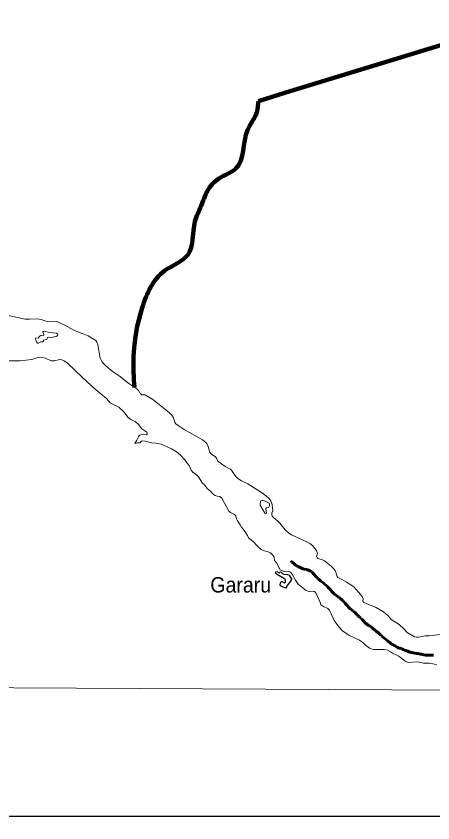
# Model space of a CAD drawing. Extents: x -1643653 to 4543381, y 1624270 to 13878484.
# Drawn here: x 701363 to 714916, y 8889633 to 8915829 of the extents above; entities that cross this region are included whole.
import ezdxf

# ---------------------------------------------------------------- set-up
doc = ezdxf.new("R2010")
doc.units = 0
doc.header["$LTSCALE"] = 200
doc.linetypes.add('LONG_DASH_SHORT_DASH', pattern=[9.9, 6, -1.2, 1.5, -1.2])
for name, color, linetype, lineweight in [('1', 7, 'Continuous', 13), ('21', 7, 'Continuous', 25), ('25', 7, 'Continuous', 13), ('3', 7, 'Continuous', 13), ('60', 7, 'Continuous', 13), ('7', 7, 'LONG_DASH_SHORT_DASH', 60), ('9', 7, 'Continuous', 90)]:
    doc.layers.add(name, color=color, linetype=linetype, lineweight=lineweight)
doc.layers.add('41', color=7, linetype='Continuous')

msp = doc.modelspace()

# ---------------------------------------------------------------- linework, layer by layer
at = {"layer": '1'}
msp.add_lwpolyline([(564751.7, 8894587.5), (664411.9, 8894209.9), (791388.5, 8893536.2)], dxfattribs=at)
at = {"layer": '21'}
msp.add_lwpolyline([(710323, 8897547.4), (710310.6, 8897510.9), (710262.7, 8897448.5), (710205.4, 8897388.1), (710179.6, 8897340.9), (710149.4, 8897265.1), (710140.8, 8897256.9), (710043.9, 8897288.4), (709961.7, 8897329.1), (709947.6, 8897363.1), (709961.6, 8897429.2), (709984.2, 8897470), (709989.6, 8897472.6), (710012.7, 8897467.5), (710090.3, 8897425.2), (710122.4, 8897447.6), (710126, 8897519.8), (710103.3, 8897545.3), (710035.6, 8897588.8), (709826.1, 8897706.4), (709795.6, 8897744), (709810.8, 8897781.5), (709838, 8897800.1), (709914.9, 8897754.6), (709934.2, 8897760.9), (709942.3, 8897776.2), (709957.1, 8897785.6), (709980.8, 8897774.5), (710029.3, 8897733.8), (710072, 8897710.7), (710184.3, 8897701.5), (710239.2, 8897671.8), (710278.2, 8897623.4), (710322, 8897552.2)], close=True, dxfattribs=at)
at = {"layer": '25'}
for points in [[(699730.1, 8905870.1), (699833.6, 8905937.4), (700049.1, 8906011), (700564.9, 8906093.9), (701005.2, 8906113.6), (701154.5, 8906101.4), (701659.8, 8905992.8), (701803.5, 8905986.5), (702058.9, 8906003.4), (702175.9, 8905983.8), (702373, 8905910.6), (702436.8, 8905905.5), (702682, 8905912.8), (702942.6, 8905799.8), (703043.5, 8905742.3)], [(703043.5, 8905742.3), (703240.1, 8905630.3), (703386.8, 8905567), (703544.9, 8905514.5)], [(703544.9, 8905514.5), (703544.9, 8905514.5), (703708.6, 8905443.2), (703903.3, 8905333.4), (703950.4, 8905293.2), (703983.7, 8905242.4), (704017.5, 8905157.8), (704100.5, 8904727.4), (704116.7, 8904678.1), (704169.6, 8904585.4), (704276.9, 8904471.4), (704483.1, 8904302.2), (704709.8, 8904149.5), (705025.3, 8903904.5), (705294.1, 8903731.4), (705355.9, 8903661.9), (705397.8, 8903579.9), (705416.3, 8903559.4), (705456.6, 8903537.1), (705545.2, 8903528.8), (705574.6, 8903518.8), (705812.1, 8903380.7), (705964.1, 8903265.1), (706335.8, 8902958.3), (706429, 8902870.5), (706478.4, 8902782.6), (706522.3, 8902644.6), (706561.4, 8902592.6), (706627.5, 8902537.3), (706829.4, 8902410.4), (707426.7, 8902069.6), (707536.7, 8901989.7), (707580.8, 8901930.1), (707613.5, 8901857.8), (707638, 8901734), (707661.4, 8901666.3), (707707.1, 8901616.1), (707849, 8901513.6), (707889.3, 8901456.4), (707921.2, 8901374.1), (708164.6, 8901203.2), (708234, 8901164.4), (708282.6, 8901144)], [(702004.3, 8904719), (701870.4, 8904678.1), (701577.9, 8904651), (701498, 8904635.9)], [(703520.5, 8904092.8), (703035.9, 8904557.4), (702930.4, 8904637.9), (702854, 8904670.9), (702784.7, 8904678.3), (702603.6, 8904639.4), (702499.6, 8904635.8), (702318.3, 8904724.9), (702212.1, 8904749.4), (702106.6, 8904750.3), (702004.3, 8904719)], [(701498, 8904635.9), (701073.3, 8904639.9), (700893.6, 8904612.2), (700683.7, 8904613.8), (700499, 8904578.5), (700435.5, 8904574.2), (700368.5, 8904593.8)], [(704418.9, 8903273.5), (704303.8, 8903412.4), (703938.7, 8903713.3), (703520.5, 8904092.8)], [(705417, 8902230.5), (705468.7, 8902243.1), (705601.7, 8902236.3), (705626.1, 8902249.9), (705630.1, 8902294), (705613.1, 8902318.7), (705450.5, 8902433.4), (705338.6, 8902571.8), (705237.8, 8902662.7), (705098.5, 8902732.8), (705008.4, 8902794.2), (704859.8, 8902995.3), (704700.7, 8903136.3), (704418.9, 8903273.5)], [(705223.5, 8901956.6), (705285.9, 8902055.5), (705327.2, 8902145.4), (705340, 8902163.9), (705340, 8902163.9)], [(705340, 8902163.9), (705380.2, 8902221.5), (705417, 8902230.5)], [(706917, 8901328.8), (706845.7, 8901419), (706706.3, 8901570.6), (706577.5, 8901683.7), (706418, 8901776), (706077.6, 8901924.8), (705902.1, 8901964.8), (705769.4, 8901975.3), (705559.8, 8902024.1), (705462.6, 8902034.1), (705436.9, 8902022.7), (705383.9, 8901976.1), (705305.7, 8901975.9), (705223.5, 8901956.6)], [(708884.8, 8898960.2), (708812.9, 8899081.1), (708692, 8899230.3), (708649.9, 8899313.3), (708562.2, 8899440.2), (708534.2, 8899502.9), (708503.8, 8899608.4), (708465.9, 8899644.1), (708336.8, 8899710.3), (708284.4, 8899750.1), (708047.8, 8900175.7), (707990.8, 8900226.5), (707897.1, 8900236.8), (707831, 8900260), (707784.3, 8900295.7), (707679.2, 8900403.7), (707579.3, 8900485.4), (707498.4, 8900600.3), (707426.9, 8900668.2), (707296.2, 8900870.2), (707244.9, 8900923.6), (707114.9, 8901025.9), (707060.8, 8901088.8), (706991.1, 8901234.8), (706917, 8901328.8)], [(708282.6, 8901144), (708331.2, 8901123.5), (708369.6, 8901088.6), (708444.9, 8900971.6), (708520.8, 8900871.2), (708577.2, 8900819.4), (708690.2, 8900735.5), (708901.9, 8900638.8), (709137.2, 8900490.7)], [(709137.2, 8900490.7), (709372.6, 8900342.6), (709571.9, 8900187.3), (709610.7, 8900136.5)], [(709610.7, 8900136.5), (709649.5, 8900085.8), (709687.8, 8899966.6), (709696.9, 8899867.4)], [(709696.9, 8899867.4), (709706, 8899768.3), (709680, 8899695), (709673.6, 8899642.5), (709691.5, 8899588), (709738.8, 8899535.9), (709875.6, 8899429.5), (709875.6, 8899429.5), (709939.8, 8899367.7), (710112.9, 8899145), (710229.9, 8899043.2), (710316.3, 8898983), (710434.5, 8898930.1)], [(709950.2, 8897853.8), (709826.5, 8898078.7), (709765, 8898154.3), (709755.6, 8898257.5), (709714.4, 8898328.8), (709634.6, 8898396.5), (709559.8, 8898439.4), (709395, 8898473.4), (709333.8, 8898506.8), (709214.9, 8898614.3), (709070.8, 8898765.5), (708925, 8898892.5), (708884.8, 8898960.2)], [(710434.5, 8898930.1), (710835, 8898750.5), (710918.4, 8898699.6), (711013.8, 8898623.8), (711070, 8898553.2)], [(711070, 8898553.2), (711126.2, 8898482.6), (711144.3, 8898448), (711158.3, 8898389.2), (711130.3, 8898282.3), (711152.8, 8898240), (711175.8, 8898222.2), (711302.1, 8898183.8), (711391.3, 8898138.3), (711554.3, 8898011), (711603.7, 8897966)], [(711603.7, 8897966), (711680.2, 8897896.3), (711746, 8897808.5), (711799.4, 8897633.4), (711822.1, 8897601.2), (711960, 8897533.9), (712103.8, 8897448.7)], [(710692.4, 8897249.1), (710533.9, 8897388.5), (710451.3, 8897511.8), (710342.9, 8897708), (710286.4, 8897777.2), (710220.4, 8897794.9), (710145.3, 8897789.3), (710079.5, 8897794.7), (709950.2, 8897853.8)], [(712103.8, 8897448.7), (712242.6, 8897366.3), (712359.3, 8897283.4), (712565.7, 8897048.4), (712631.8, 8896958.1), (712647.9, 8896909.4), (712637.9, 8896831.9), (712665.2, 8896790.9), (712768.3, 8896741.4), (713044.9, 8896638.8), (713311.2, 8896489.3), (713385.5, 8896424.1)], [(711124.5, 8897078.8), (711093, 8897127.9), (711068.7, 8897147.8), (711049.5, 8897152.8), (710908.8, 8897146.9), (710849.4, 8897155.7), (710797.6, 8897180.7), (710692.4, 8897249.1)], [(712525.7, 8895564.3), (712179.3, 8895726.8), (711977.5, 8895873.7), (711872.3, 8895986), (711707.5, 8896200.3), (711600.3, 8896454.3), (711553.8, 8896536.9), (711494.9, 8896598.8), (711354.3, 8896661.8), (711292.1, 8896701.3), (711270.5, 8896704.9), (711261.3, 8896763.5), (711124.5, 8897078.8)], [(713385.5, 8896424.1), (713459.8, 8896359), (713569.8, 8896225.6), (713696.9, 8896155.1), (713818.3, 8896075.1), (713842, 8896053.8)], [(713842, 8896053.8), (713946.1, 8895960.1), (714080.1, 8895815.7), (714321.1, 8895672.2), (714384.5, 8895659.7), (714451.9, 8895662.4), (714514.6, 8895674.6)], [(713532.7, 8895186.2), (713435.1, 8895242.8), (713335.4, 8895258.7), (712968.6, 8895262), (712859.7, 8895301.9), (712725.3, 8895401.6), (712648.5, 8895483.1), (712525.7, 8895564.3)], [(714514.6, 8895674.6), (714664.7, 8895703.8), (714810.4, 8895708.8), (715055.3, 8895739.1), (715289.1, 8895748.2), (715407.8, 8895761.9)], [(715039.1, 8894760), (714963.6, 8894786.5), (714790.6, 8894820), (714606.1, 8894818.8), (714473.2, 8894853.3), (714404.1, 8894859.6), (714116.9, 8894843.6), (714034.5, 8894876.8), (713967, 8894916.7), (713850.5, 8895013.2), (713789.1, 8895053.9), (713604, 8895144.8), (713532.7, 8895186.2)]]:
    msp.add_lwpolyline(points, dxfattribs=at)
for points in [[(702679.3, 8905532.6), (702433.7, 8905559), (702292.5, 8905598.5), (702244.4, 8905591.1), (702234.6, 8905581.9), (702232, 8905562.8), (702259.6, 8905493.7), (702249.4, 8905443.2), (702159.4, 8905461.2), (702115.8, 8905419.6), (702084.4, 8905369.4), (702001, 8905388), (701998, 8905341.8), (702023.2, 8905250.2), (702057, 8905211), (702086.6, 8905207.7), (702162.1, 8905255.6), (702214.5, 8905249.9), (702235, 8905255.7), (702269.6, 8905309.9), (702336.8, 8905325.8), (702376.9, 8905350), (702388.8, 8905392.2), (702403.4, 8905405.1), (702532.1, 8905397.2), (702600.3, 8905416.2), (702662.5, 8905423.3), (702700.1, 8905446), (702715.3, 8905477.1), (702706.1, 8905515.4)], [(709580.3, 8899889.8), (709596.2, 8899906.3), (709606, 8899943.5), (709599.7, 8899997.3), (709588.6, 8900017.3), (709459.5, 8900083.7), (709393.7, 8900104.9), (709351.6, 8900105.7), (709323, 8900086.1), (709294.9, 8900014.3), (709301.9, 8899949.1), (709327.1, 8899890.5), (709454.5, 8899688.2), (709485.7, 8899677.3), (709503.8, 8899701.2), (709483.4, 8899821.2), (709487.6, 8899841.5), (709510.1, 8899860.5)]]:
    msp.add_lwpolyline(points, close=True, dxfattribs=at)
at = {"layer": '3', "lineweight": 25}
msp.add_lwpolyline([(563033.9, 9026438.8), (793061.1, 9026438.8), (793495.6, 8889836.8), (563468.3, 8889836.8)], close=True, dxfattribs=at)
at = {"layer": '60', "lineweight": 25}
msp.add_spline([(814781, 9009175.5), (814787.2, 9009173.4), (814796.9, 9009173.4), (814799.4, 9009172.4), (814805.1, 9009174.5), (814805.6, 9009176.5), (814811.7, 9009179.5), (814811.7, 9009179.5), (814801.5, 9009181), (814790.7, 9009181.5), (814784.1, 9009183.1), (814777.4, 9009185.1), (814778.4, 9009175.5)], degree=3, dxfattribs=at)
at = {"layer": '7'}
for points in [[(711474.4, 8897314.1), (711433.6, 8897355), (711398, 8897378), (711370, 8897413.8), (711308.9, 8897454.7), (711270.7, 8897477.7), (711230, 8897521.1), (711189.3, 8897549.2), (711148.6, 8897600.3), (711112.9, 8897631), (711056.9, 8897694.9), (711016.2, 8897746.1), (710965.3, 8897792.1), (710911.8, 8897817.6), (710817.7, 8897856), (710718.5, 8897873.8), (710647.2, 8897904.5), (710598.8, 8897925), (710555.6, 8897945.4), (710507.2, 8897965.9), (710481.8, 8897986.3), (710448.7, 8898001.7), (710413.1, 8898034.9), (710374.9, 8898073.2), (710334.2, 8898098.8), (710296.3, 8898144.4)], [(712701.2, 8896140.8), (712675.8, 8896166.4), (712632.5, 8896220.1), (712599.4, 8896243.1), (712581.6, 8896276.3), (712546, 8896294.2), (712525.6, 8896327.4), (712487.4, 8896347.9), (712467.1, 8896388.8), (712431.4, 8896414.3), (712375.4, 8896475.7), (712327.1, 8896498.7), (712276.2, 8896547.2), (712230.3, 8896585.6), (712176.9, 8896636.7), (712146.3, 8896664.8), (712110.7, 8896708.3), (712075.1, 8896746.6), (712052.2, 8896784.9), (712016.5, 8896805.4), (711996.2, 8896843.7), (711960.5, 8896861.6), (711924.9, 8896910.2), (711889.3, 8896928.1), (711866.3, 8896958.8), (711830.7, 8896976.7), (711795.1, 8897009.9), (711759.5, 8897027.8), (711718.7, 8897061), (711695.8, 8897081.5), (711657.6, 8897112.1), (711619.5, 8897158.2), (711594, 8897186.3), (711555.8, 8897232.3), (711532.9, 8897257.8), (711497.3, 8897291.1), (711474.4, 8897314.1)], [(714935.7, 8895082.6), (714900.1, 8895077.5), (714841.5, 8895077.5), (714803.3, 8895077.5), (714762.7, 8895077.5), (714739.7, 8895077.5), (714701.6, 8895080), (714673.6, 8895082.6), (714625.2, 8895090.3), (714582, 8895097.9), (714541.3, 8895105.6), (714503.1, 8895113.3), (714464.9, 8895120.9), (714431.8, 8895128.6), (714391.1, 8895136.3), (714332.6, 8895143.9), (714279.2, 8895159.3), (714230.8, 8895166.9), (714185, 8895166.9), (714144.3, 8895187.4), (714096, 8895205.3), (714055.2, 8895220.6), (714034.9, 8895225.7), (714004.3, 8895241.1), (713984, 8895246.2), (713945.8, 8895264.1), (713922.9, 8895269.2), (713889.8, 8895289.6), (713851.6, 8895307.5), (713808.4, 8895310.1), (713762.6, 8895328), (713732, 8895345.9), (713693.9, 8895376.5), (713653.1, 8895391.9), (713612.4, 8895425.1), (713569.2, 8895440.4), (713541.2, 8895471.1), (713503, 8895496.7), (713467.3, 8895527.3), (713429.2, 8895547.8), (713403.7, 8895581), (713370.6, 8895601.5), (713324.8, 8895642.4), (713273.9, 8895670.5), (713248.5, 8895716.5), (713210.3, 8895739.5), (713177.2, 8895775.3), (713131.4, 8895811.1), (713098.3, 8895831.5), (713057.6, 8895869.9), (713032.1, 8895885.2), (712991.4, 8895918.4), (712968.5, 8895933.8), (712930.3, 8895972.1), (712871.8, 8896020.7), (712828.5, 8896033.5), (712787.8, 8896074.3), (712747.1, 8896094.8), (712701.2, 8896140.8)]]:
    msp.add_lwpolyline(points, dxfattribs=at)
at = {"layer": '9'}
for p, q in [((710134.6, 8913345.1), (715561.4, 8915010.8)), ((709242.2, 8913071.2), (710135.7, 8913345.4))]:
    msp.add_line(p, q, dxfattribs=at)
msp.add_spline([(705207.9, 8903769.6), (705180.7, 8904747.4), (705463.8, 8906360), (706198.7, 8907564.6), (706955.5, 8908091.1), (707178.8, 8909156.3), (707379.5, 8909664.2), (707580.3, 8910146.8), (707959.3, 8910554.8), (708516.4, 8910888.1), (708891.3, 8912131.7), (709193.2, 8912716.3), (709242.2, 8913071.2)], degree=3, dxfattribs=at)

# ---------------------------------------------------------------- texts
at = {"layer": '41', "width": 0.95}
msp.add_text('Gararu', height=500, dxfattribs=at).set_placement((707678.8, 8897112.8))

doc.saveas('drawing.dxf')
